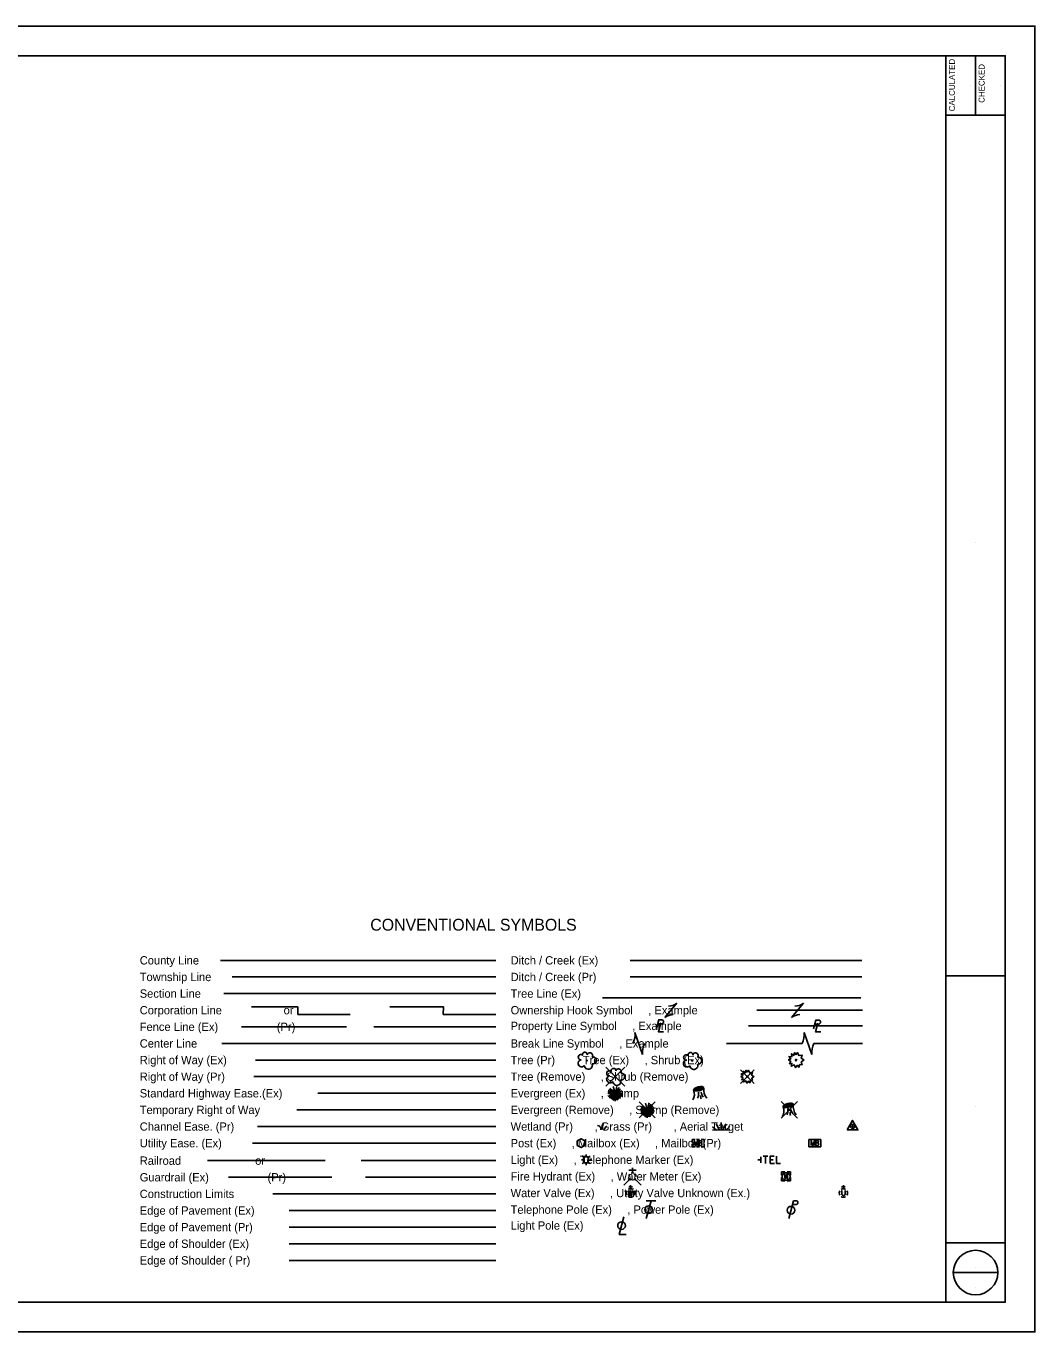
# Model space of a CAD drawing. Extents: x 0 to 34, y 0 to 29.7.
# Drawn here: x 17 to 34, y 0 to 22 of the extents above; entities that cross this region are included whole.
import ezdxf

# ---------------------------------------------------------------- set-up
doc = ezdxf.new("R2010")
doc.units = 0
for name, color, linetype in [('SH_Border', 7, 'Continuous'), ('SH_Cut_Line', 7, 'Continuous'), ('SH_Data', 7, 'Continuous'), ('SH_Text', 7, 'Continuous')]:
    doc.layers.add(name, color=color, linetype=linetype)

msp = doc.modelspace()

# ---------------------------------------------------------------- linework, layer by layer
at = {"layer": 'SH_Border'}
for p, q in [((32.5, 0.5), (32.5, 21.5)), ((33, 21.5), (33, 20.5)), ((32.5, 20.5), (33.5, 20.5)), ((32.5, 6), (33.5, 6)), ((32.5, 1.5), (33.5, 1.5))]:
    msp.add_line(p, q, dxfattribs=at)
msp.add_lwpolyline([(2, 21.5), (33.5, 21.5), (33.5, 0.5), (2, 0.5)], close=True, dxfattribs=at)
at = {"layer": 'SH_Cut_Line'}
msp.add_lwpolyline([(0, 0), (34, 0), (34, 22), (0, 22)], close=True, dxfattribs=at)
at = {"layer": 'SH_Data'}
for p, q in [((32.92, 21.004), (32.92, 21.004)), ((33.42, 21.004), (33.42, 21.004)), ((33, 13.292), (33, 13.292)), ((33, 3.792), (33, 3.792)), ((32.625, 1), (33.375, 1)), ((33, 1.085), (33, 1.085)), ((33, 0.745), (33, 0.745))]:
    msp.add_line(p, q, dxfattribs=at)
msp.add_circle((33, 1), 0.375, dxfattribs=at)
at = {"layer": 'SH_Text'}
for p, q in [((20.276, 6.26), (24.915, 6.26)), ((27.182, 6.26), (31.082, 6.26)), ((20.475, 5.98), (24.915, 5.98)), ((27.182, 5.98), (31.082, 5.98)), ((20.332, 5.7), (24.915, 5.7)), ((26.714, 5.63), (31.064, 5.63)), ((27.766, 5.297), (27.966, 5.537)), ((29.898, 5.297), (30.098, 5.537)), ((20.796, 5.476), (21.578, 5.476)), ((21.578, 5.476), (21.578, 5.35)), ((21.578, 5.35), (22.459, 5.35)), ((27.866, 5.417), (27.866, 5.417)), ((29.312, 5.42), (31.094, 5.42)), ((29.998, 5.417), (29.998, 5.417)), ((20.629, 5.14), (22.402, 5.14)), ((22.859, 5.14), (24.915, 5.14)), ((27.642, 5.189), (27.707, 5.189)), ((27.682, 5.158), (27.682, 5.158)), ((29.171, 5.155), (31.094, 5.155)), ((30.291, 5.185), (30.356, 5.185)), ((30.331, 5.154), (30.331, 5.154)), ((20.297, 4.86), (24.915, 4.86)), ((27.26, 5.044), (27.39, 4.676)), ((27.325, 4.86), (27.325, 4.86)), ((28.801, 4.86), (30.077, 4.86)), ((30.112, 5.044), (30.242, 4.676)), ((30.177, 4.86), (30.177, 4.86)), ((30.277, 4.86), (31.094, 4.86)), ((20.865, 4.58), (24.915, 4.58)), ((26.767, 4.46), (27.088, 4.14)), ((27.088, 4.46), (26.767, 4.14)), ((29.038, 4.416), (29.27, 4.184)), ((29.27, 4.416), (29.038, 4.184)), ((20.837, 4.3), (24.915, 4.3)), ((26.928, 4.3), (26.928, 4.3)), ((29.154, 4.3), (29.154, 4.3)), ((21.915, 4.02), (24.915, 4.02)), ((26.802, 4.02), (26.925, 4.02)), ((26.925, 4.02), (26.815, 4.049)), ((26.925, 4.02), (26.818, 3.981)), ((26.925, 4.02), (26.826, 3.963)), ((26.925, 4.02), (26.828, 4.077)), ((26.925, 4.02), (26.828, 3.945)), ((26.925, 4.02), (26.838, 4.107)), ((26.925, 4.02), (26.852, 3.933)), ((26.925, 4.02), (26.867, 3.919)), ((26.925, 4.02), (26.884, 3.911)), ((26.925, 4.02), (26.894, 3.898)), ((26.925, 4.02), (26.895, 4.135)), ((26.925, 4.02), (26.912, 3.905)), ((26.925, 4.02), (26.957, 4.137)), ((26.925, 4.02), (26.992, 4.117)), ((26.925, 4.02), (27.017, 4.09)), ((26.925, 4.02), (27.044, 4.06)), ((26.925, 4.02), (27.038, 4.022)), ((26.925, 3.889), (26.925, 4.02)), ((26.925, 4.02), (26.948, 3.904)), ((26.925, 4.02), (26.974, 3.903)), ((26.925, 4.02), (26.989, 3.925)), ((26.925, 4.02), (27.015, 3.932)), ((26.925, 4.02), (27.021, 3.956)), ((26.925, 4.02), (27.037, 3.971)), ((26.925, 4.02), (27.046, 3.996)), ((28.353, 4.02), (28.353, 4.02)), ((27.334, 3.874), (27.602, 3.606)), ((27.602, 3.874), (27.334, 3.606)), ((27.468, 3.74), (27.358, 3.77)), ((27.468, 3.74), (27.37, 3.797)), ((27.468, 3.74), (27.381, 3.827)), ((27.468, 3.74), (27.437, 3.855)), ((27.468, 3.74), (27.499, 3.857)), ((27.468, 3.74), (27.534, 3.837)), ((27.468, 3.74), (27.559, 3.81)), ((27.468, 3.74), (27.586, 3.78)), ((27.468, 3.74), (27.581, 3.742)), ((29.722, 3.879), (30, 3.601)), ((30, 3.879), (29.722, 3.601)), ((29.861, 3.74), (29.861, 3.74)), ((21.561, 3.74), (24.915, 3.74)), ((27.345, 3.74), (27.468, 3.74)), ((27.468, 3.74), (27.361, 3.701)), ((27.468, 3.74), (27.368, 3.683)), ((27.468, 3.74), (27.37, 3.665)), ((27.468, 3.74), (27.394, 3.653)), ((27.468, 3.74), (27.41, 3.64)), ((27.468, 3.74), (27.426, 3.631)), ((27.468, 3.74), (27.436, 3.619)), ((27.468, 3.74), (27.455, 3.625)), ((27.468, 3.609), (27.468, 3.74)), ((27.468, 3.74), (27.491, 3.624)), ((27.468, 3.74), (27.516, 3.623)), ((27.468, 3.74), (27.531, 3.645)), ((27.468, 3.74), (27.558, 3.652)), ((27.468, 3.74), (27.564, 3.676)), ((27.468, 3.74), (27.58, 3.691)), ((27.468, 3.74), (27.589, 3.716)), ((27.468, 3.74), (27.468, 3.74)), ((28.713, 3.4), (28.712, 3.525)), ((29.861, 3.74), (29.861, 3.74)), ((20.898, 3.46), (24.915, 3.46)), ((28.635, 3.399), (28.566, 3.456)), ((28.567, 3.398), (28.859, 3.402)), ((28.683, 3.4), (28.631, 3.506)), ((28.743, 3.4), (28.792, 3.508)), ((28.792, 3.401), (28.859, 3.46)), ((20.815, 3.18), (24.915, 3.18)), ((28.3, 3.241), (28.35, 3.241)), ((28.3, 3.119), (28.35, 3.119)), ((28.325, 3.18), (28.325, 3.18)), ((30.292, 3.18), (30.292, 3.18)), ((20.054, 2.885), (22.04, 2.885)), ((22.649, 2.885), (24.915, 2.885)), ((26.388, 2.9), (26.361, 2.9)), ((26.392, 2.948), (26.373, 2.967)), ((26.44, 2.964), (26.44, 2.991)), ((26.44, 2.9), (26.44, 2.9)), ((26.507, 2.967), (26.488, 2.948)), ((26.519, 2.9), (26.492, 2.9)), ((29.381, 2.9), (29.331, 2.9)), ((29.381, 2.85), (29.381, 2.95)), ((26.392, 2.852), (26.373, 2.833)), ((26.44, 2.836), (26.44, 2.809)), ((26.507, 2.833), (26.488, 2.852)), ((27.279, 2.723), (27.159, 2.723)), ((27.219, 2.68), (27.219, 2.766)), ((20.408, 2.605), (22.15, 2.605)), ((22.72, 2.605), (24.915, 2.605)), ((27.177, 2.578), (27.073, 2.474)), ((27.219, 2.442), (27.156, 2.442)), ((27.188, 2.41), (27.188, 2.474)), ((27.219, 2.62), (27.219, 2.62)), ((27.219, 2.62), (27.219, 2.62)), ((27.261, 2.578), (27.365, 2.474)), ((29.806, 2.62), (29.806, 2.62)), ((30.805, 2.442), (30.741, 2.442)), ((30.773, 2.41), (30.773, 2.473)), ((21.159, 2.325), (24.915, 2.325)), ((27.188, 2.34), (27.188, 2.34)), ((27.532, 2.21), (27.451, 1.91)), ((27.612, 2.21), (27.452, 2.21)), ((29.933, 2.21), (29.852, 1.91)), ((29.933, 2.21), (29.975, 2.21)), ((30.746, 2.383), (30.746, 2.314)), ((30.773, 2.34), (30.773, 2.34)), ((30.8, 2.383), (30.8, 2.314)), ((21.432, 2.045), (24.915, 2.045)), ((29.916, 2.146), (29.975, 2.146)), ((21.432, 1.765), (24.915, 1.765)), ((21.432, 1.485), (24.915, 1.485)), ((21.432, 1.205), (24.915, 1.205))]:
    msp.add_line(p, q, dxfattribs=at)
for points in [[(23.132, 5.476), (24.036, 5.476), (24.03, 5.35), (24.915, 5.35)], [(27.621, 5.109), (27.66, 5.258), (27.712, 5.258)], [(27.696, 5.206), (27.656, 5.058), (27.743, 5.058)], [(30.27, 5.106), (30.309, 5.254), (30.361, 5.254)], [(30.344, 5.202), (30.305, 5.054), (30.392, 5.054)], [(29.971, 4.67), (30.001, 4.707), (30.022, 4.655), (30.076, 4.664), (30.059, 4.613), (30.107, 4.583), (30.064, 4.546), (30.076, 4.501), (30.039, 4.504), (30.022, 4.459), (30.001, 4.493), (29.967, 4.452), (29.946, 4.497), (29.895, 4.475), (29.904, 4.522), (29.864, 4.518), (29.887, 4.558), (29.849, 4.586), (29.886, 4.599), (29.856, 4.639), (29.902, 4.634), (29.901, 4.686), (29.938, 4.657), (29.949, 4.707), (29.971, 4.67)], [(29.15, 4.377), (29.176, 4.408), (29.194, 4.363), (29.24, 4.371), (29.226, 4.328), (29.266, 4.303), (29.229, 4.272), (29.24, 4.233), (29.208, 4.236), (29.194, 4.197), (29.176, 4.226), (29.147, 4.191), (29.129, 4.229), (29.086, 4.211), (29.094, 4.251), (29.059, 4.247), (29.079, 4.281), (29.047, 4.305), (29.078, 4.316), (29.052, 4.35), (29.092, 4.346), (29.091, 4.39), (29.123, 4.366), (29.131, 4.408), (29.15, 4.377)], [(26.287, 3.142), (26.352, 3.105), (26.417, 3.142), (26.417, 3.217), (26.352, 3.255), (26.287, 3.217), (26.287, 3.142)], [(28.225, 3.193), (28.225, 3.241), (28.274, 3.241)], [(28.274, 3.119), (28.225, 3.119), (28.225, 3.167)], [(28.26, 3.14), (28.26, 3.22), (28.289, 3.14), (28.317, 3.22), (28.317, 3.14)], [(28.376, 3.183), (28.379, 3.187), (28.381, 3.189), (28.382, 3.19), (28.383, 3.192), (28.384, 3.194), (28.385, 3.196), (28.386, 3.2), (28.386, 3.202), (28.386, 3.205), (28.386, 3.209), (28.384, 3.212), (28.382, 3.214), (28.379, 3.217), (28.377, 3.218), (28.376, 3.219), (28.372, 3.22), (28.342, 3.22), (28.342, 3.14), (28.376, 3.14), (28.381, 3.143), (28.384, 3.146), (28.388, 3.151), (28.389, 3.156), (28.39, 3.162), (28.39, 3.166), (28.389, 3.17), (28.386, 3.175), (28.383, 3.179), (28.376, 3.183), (28.342, 3.183)], [(28.375, 3.241), (28.425, 3.241), (28.425, 3.193)], [(28.425, 3.167), (28.425, 3.119), (28.375, 3.119)], [(30.227, 3.14), (30.227, 3.22), (30.256, 3.14), (30.284, 3.22), (30.284, 3.14)], [(30.343, 3.183), (30.346, 3.187), (30.348, 3.189), (30.349, 3.19), (30.35, 3.192), (30.351, 3.194), (30.352, 3.196), (30.353, 3.2), (30.353, 3.202), (30.353, 3.205), (30.353, 3.209), (30.351, 3.212), (30.349, 3.214), (30.346, 3.217), (30.344, 3.218), (30.343, 3.219), (30.339, 3.22), (30.308, 3.22), (30.308, 3.14), (30.343, 3.14), (30.348, 3.143), (30.351, 3.146), (30.354, 3.151), (30.356, 3.156), (30.357, 3.162), (30.357, 3.166), (30.356, 3.17), (30.353, 3.175), (30.35, 3.179), (30.343, 3.183), (30.308, 3.183)], [(29.422, 2.962), (29.499, 2.962)], [(29.461, 2.962), (29.461, 2.837)], [(29.607, 2.962), (29.539, 2.962), (29.539, 2.837), (29.612, 2.837)], [(29.539, 2.9), (29.587, 2.9)], [(29.646, 2.962), (29.646, 2.837), (29.714, 2.837)], [(29.786, 2.695), (29.731, 2.695), (29.731, 2.64)], [(29.773, 2.665), (29.789, 2.575), (29.806, 2.665), (29.823, 2.575), (29.839, 2.665)], [(29.881, 2.64), (29.881, 2.695), (29.826, 2.695)], [(29.731, 2.6), (29.731, 2.545), (29.786, 2.545)], [(29.826, 2.545), (29.881, 2.545), (29.881, 2.6)], [(27.156, 2.381), (27.172, 2.295), (27.188, 2.381), (27.204, 2.295), (27.219, 2.381)], [(27.073, 1.939), (26.995, 1.639), (27.113, 1.639)]]:
    msp.add_lwpolyline(points, dxfattribs=at)
for points in [[(30.837, 3.402), (31.017, 3.402), (30.927, 3.563)], [(30.192, 3.241), (30.392, 3.241), (30.392, 3.119), (30.192, 3.119)], [(26.407, 2.85), (26.473, 2.85), (26.473, 2.95), (26.407, 2.95)]]:
    msp.add_lwpolyline(points, close=True, dxfattribs=at)
for centre, radius in [((26.447, 4.572), 0.0084), ((28.224, 4.568), 0.0072), ((29.975, 4.58), 0.0115), ((26.928, 4.3), 0.0072), ((29.154, 4.3), 0.00979), ((30.927, 3.46), 0.035), ((30.927, 3.46), 0.008), ((29.806, 2.62), 0.0675), ((27.491, 2.06), 0.065), ((29.89, 2.05), 0.065), ((27.034, 1.791), 0.065)]:
    msp.add_circle(centre, radius, dxfattribs=at)
for centre, radius, start, end in [((27.808, 5.752), 0.267, 273.6945, 306.337), ((29.94, 5.752), 0.267, 273.6945, 306.337), ((27.924, 5.082), 0.267, 93.6945, 126.337), ((30.056, 5.082), 0.267, 93.6945, 126.337), ((27.707, 5.223), 0.0345, 270.471, 81.3281), ((30.355, 5.22), 0.0345, 270.471, 81.3281), ((26.928, 5.012), 0.334, 332.9422, 5.5848), ((27.722, 4.708), 0.334, 152.9422, 185.5848), ((29.78, 5.012), 0.334, 332.9422, 5.5848), ((30.574, 4.708), 0.334, 152.9422, 185.5848), ((26.348, 4.628), 0.0441, 39.0625, 279.5412), ((26.417, 4.673), 0.0395, 354.0047, 205.9741), ((26.502, 4.657), 0.0466, 323.83, 165.0376), ((26.551, 4.573), 0.0574, 259.1453, 101.4596), ((28.125, 4.624), 0.0441, 39.0625, 279.5412), ((28.195, 4.669), 0.0395, 354.0047, 205.9741), ((28.279, 4.653), 0.0466, 323.83, 165.0376), ((28.328, 4.57), 0.0574, 259.1453, 101.4596), ((26.361, 4.525), 0.0592, 96.1722, 320.5737), ((26.475, 4.494), 0.0685, 184.9476, 19.4572), ((26.828, 4.356), 0.0441, 39.0625, 279.5412), ((26.898, 4.401), 0.0395, 354.0047, 205.9741), ((26.982, 4.385), 0.0466, 323.83, 165.0376), ((28.138, 4.522), 0.0592, 96.1722, 320.5737), ((28.252, 4.49), 0.0685, 184.9476, 19.4572), ((26.842, 4.254), 0.0592, 96.1722, 320.5737), ((26.956, 4.222), 0.0685, 184.9476, 19.4572), ((27.031, 4.301), 0.0574, 259.1453, 101.4596), ((28.062, 4.003), 0.2, 331.5338, 20.9269), ((28.078, 4.021), 0.253, 340.7938, 3.5481), ((28.549, 3.98), 0.182, 178.7926, 197.1224), ((28.679, 4.123), 0.316, 194.9653, 212.1216), ((28.634, 4.077), 0.215, 171.4106, 219.9194), ((29.57, 3.723), 0.2, 331.5338, 20.9269), ((29.585, 3.741), 0.253, 340.7938, 3.5481), ((30.187, 3.843), 0.316, 194.9653, 212.1216), ((30.142, 3.797), 0.215, 171.4106, 219.9194), ((30.056, 3.7), 0.182, 178.7926, 197.1224), ((27.219, 2.62), 0.06, 140.021, 184.0629), ((27.219, 2.62), 0.06, 68.1395, 112.038), ((27.219, 2.62), 0.06, 356.0165, 39.9889), ((27.219, 2.62), 0.06, 211.8788, 255.8479), ((27.219, 2.62), 0.06, 283.8239, 329.9097), ((27.188, 2.34), 0.07, 150.0184, 209.9816), ((27.188, 2.34), 0.07, 60.0184, 120.0157), ((27.188, 2.34), 0.07, 239.9843, 299.9816), ((27.188, 2.34), 0.07, 330.0184, 29.9816), ((29.976, 2.178), 0.0319, 268.8767, 91.1233), ((30.773, 2.34), 0.07, 150.0184, 209.9816), ((30.773, 2.34), 0.07, 60.0184, 120.0157), ((30.773, 2.34), 0.07, 239.9843, 299.9816), ((30.773, 2.327), 0.03, 205.1924, 334.8076), ((30.773, 2.34), 0.07, 330.0184, 29.9816)]:
    msp.add_arc(centre, radius, start, end, dxfattribs=at)
for centre, major_axis in [((28.335, 4.096), (0.0868, 0.0187)), ((28.335, 4.096), (0.0651, 0.0141)), ((28.335, 4.096), (0.0488, 0.0105)), ((28.335, 4.096), (0.0275, 0.0059)), ((28.335, 4.096), (0.0154, 0.0033)), ((29.842, 3.816), (0.0868, 0.0187)), ((29.842, 3.816), (0.0651, 0.0141)), ((29.842, 3.816), (0.0488, 0.0105)), ((29.842, 3.816), (0.0275, 0.0059)), ((29.842, 3.816), (0.0154, 0.0033))]:
    msp.add_ellipse(centre, major_axis=major_axis, ratio=0.36865, dxfattribs=at)
for points in [[(26.716, 3.409), (26.716, 3.456), (26.722, 3.5), (26.731, 3.521)], [(26.629, 3.476), (26.67, 3.458), (26.688, 3.405)], [(26.744, 3.401), (26.756, 3.44), (26.785, 3.464)]]:
    msp.add_spline(points, degree=3, dxfattribs=at)

# ---------------------------------------------------------------- texts
at = {"layer": 'SH_Data'}
for s, p in [('CALCULATED', (32.652, 20.565)), ('CHECKED', (33.152, 20.708))]:
    msp.add_text(s, height=0.1, rotation=90, dxfattribs=at).set_placement(p)
at = {"layer": 'SH_Text'}
for s, height, p in [('CONVENTIONAL SYMBOLS', 0.2, (22.8, 6.76)), ('County Line', 0.14, (18.915, 6.19)), ('Ditch / Creek (Ex)', 0.14, (25.165, 6.19)), ('Township Line', 0.14, (18.915, 5.91)), ('Ditch / Creek (Pr)', 0.14, (25.165, 5.91)), ('Section Line', 0.14, (18.915, 5.63)), ('Tree Line (Ex)', 0.14, (25.165, 5.63)), ('Corporation Line                    or', 0.14, (18.915, 5.35)), ('Ownership Hook Symbol     , Example', 0.14, (25.165, 5.35)), ('Fence Line (Ex)                   (Pr)', 0.14, (18.915, 5.07)), ('Property Line Symbol     , Example', 0.14, (25.165, 5.085)), ('Center Line', 0.14, (18.915, 4.79)), ('Break Line Symbol     , Example', 0.14, (25.165, 4.79)), ('Right of Way (Ex)', 0.14, (18.915, 4.51)), ('Tree (Pr)       , Tree (Ex)     , Shrub (Ex)', 0.14, (25.165, 4.51)), ('Right of Way (Pr)', 0.14, (18.915, 4.23)), ('Tree (Remove)     , Shrub (Remove)', 0.14, (25.165, 4.23)), ('Standard Highway Ease.(Ex)', 0.14, (18.915, 3.95)), ('Evergreen (Ex)     , Stump ', 0.14, (25.165, 3.95)), ('Temporary Right of Way', 0.14, (18.915, 3.67)), ('Evergreen (Remove)     , Stump (Remove)', 0.14, (25.165, 3.67)), ('Channel Ease. (Pr)', 0.14, (18.915, 3.39)), ('Wetland (Pr)       , Grass (Pr)       , Aerial Target    ', 0.14, (25.165, 3.39)), ('Utility Ease. (Ex)', 0.14, (18.915, 3.11)), ('Post (Ex)     , Mailbox (Ex)     , Mailbox (Pr)', 0.14, (25.165, 3.11)), ('Railroad                        or', 0.14, (18.915, 2.815)), ('Light (Ex)     , Telephone Marker (Ex)     ', 0.14, (25.165, 2.83)), ('Guardrail (Ex)                   (Pr)', 0.14, (18.915, 2.535)), ('Fire Hydrant (Ex)     , Water Meter (Ex)', 0.14, (25.165, 2.55)), ('Construction Limits', 0.14, (18.915, 2.255)), ('Water Valve (Ex)     , Utility Valve Unknown (Ex.)', 0.14, (25.165, 2.27)), ('Edge of Pavement (Ex)', 0.14, (18.915, 1.975)), ('Telephone Pole (Ex)     , Power Pole (Ex)', 0.14, (25.165, 1.99)), ('Edge of Pavement (Pr)', 0.14, (18.915, 1.695)), ('Light Pole (Ex)     ', 0.14, (25.165, 1.723)), ('Edge of Shoulder (Ex)', 0.14, (18.915, 1.415)), ('Edge of Shoulder ( Pr)', 0.14, (18.915, 1.135))]:
    msp.add_text(s, height=height, dxfattribs=at).set_placement(p)

doc.saveas('drawing.dxf')
